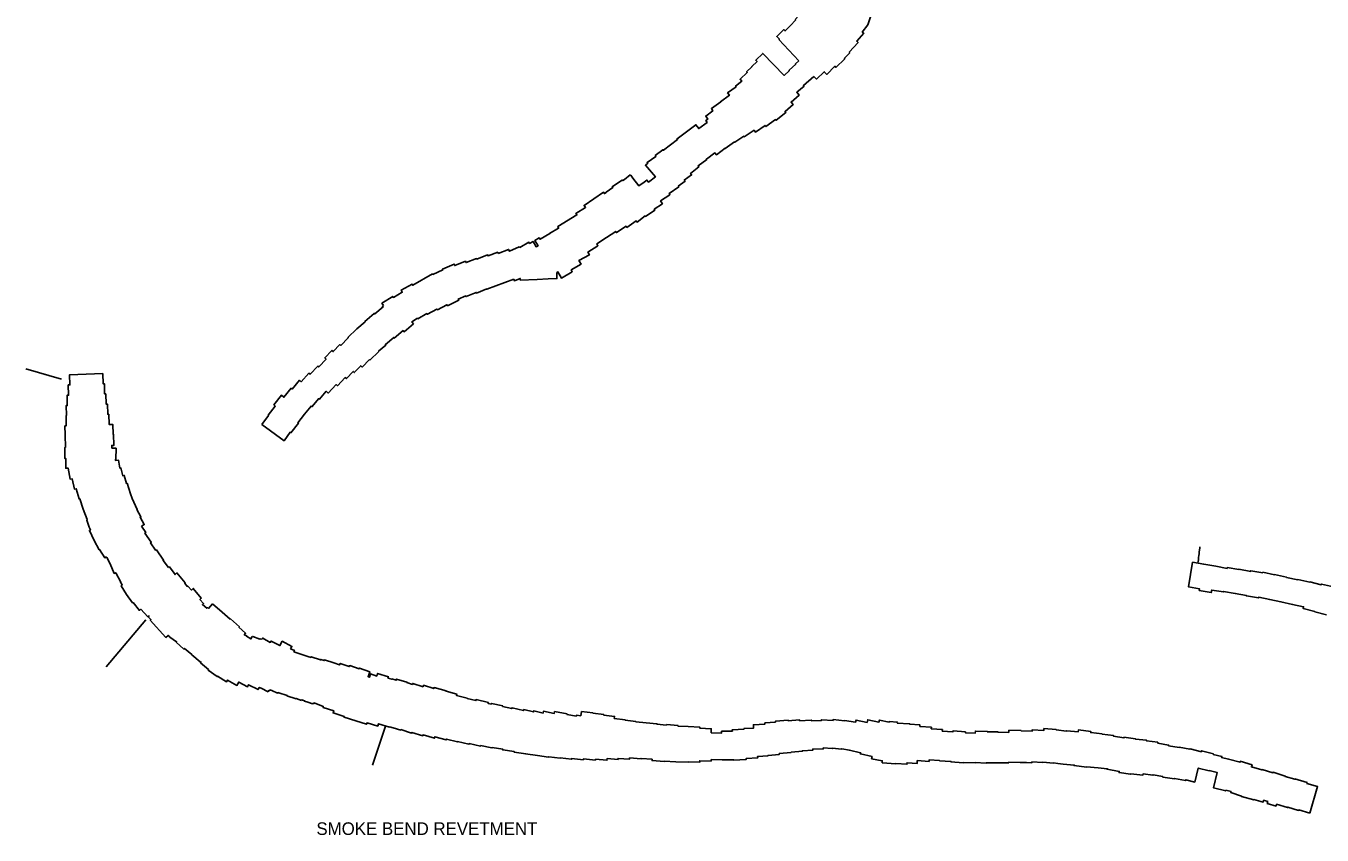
# Model space of a CAD drawing. Extents: x 2650582 to 3923188, y 277893 to 989177.
# Drawn here: x 3374386 to 3390842, y 584850 to 595125 of the extents above; entities that cross this region are included whole.
import ezdxf

# ---------------------------------------------------------------- set-up
doc = ezdxf.new("R2010")
doc.units = 0
doc.layers.add('Level 3', color=7, linetype='Continuous')

msp = doc.modelspace()

# ---------------------------------------------------------------- linework, layer by layer
at = {"layer": 'Level 3'}
for p, q in [((3374837, 590640), (3374386, 590770)), ((3375530, 589764), (3375479, 589764)), ((3375909, 587585), (3375406, 586988)), ((3377460, 586670), (3377471, 586690)), ((3378787, 585739), (3378953, 586234))]:
    msp.add_line(p, q, dxfattribs=at)
for points in [[(3384200, 594680), (3383947, 594951), (3383953, 594956), (3383919, 594992), (3384008, 595078), (3384024, 595061), (3384088, 595125), (3384087, 595126), (3384160, 595202), (3384154, 595208), (3384239, 595299), (3384248, 595290), (3384314, 595360), (3384312, 595361), (3384416, 595473), (3384440, 595450), (3384519, 595529), (3384494, 595553), (3384532, 595594)], [(3385108, 595385), (3385106, 595298), (3385125, 595292), (3385077, 595140), (3385072, 595141), (3385076, 595137), (3385004, 595047), (3385023, 595031), (3384935, 594931), (3384952, 594916), (3384839, 594790), (3384845, 594784), (3384777, 594715), (3384782, 594708), (3384669, 594598), (3384656, 594612), (3384553, 594510), (3384521, 594543), (3384423, 594450), (3384390, 594483)], [(3382376, 593481), (3382474, 593553), (3382479, 593546), (3382660, 593683), (3382654, 593692), (3382892, 593869), (3382928, 593821), (3383035, 593899), (3383019, 593924), (3383045, 593941), (3383018, 593981), (3383107, 594046), (3383090, 594075), (3383208, 594159), (3383206, 594161), (3383317, 594244), (3383295, 594275), (3383403, 594352), (3383396, 594361), (3383476, 594424), (3383453, 594448), (3383543, 594535), (3383536, 594541), (3383603, 594606), (3383601, 594608), (3383668, 594673), (3383652, 594689), (3383741, 594775), (3384011, 594496), (3384079, 594557), (3384076, 594562), (3384160, 594638), (3384156, 594643), (3384200, 594680)], [(3384390, 594483), (3384258, 594369), (3384265, 594360), (3384173, 594283), (3384202, 594245), (3384101, 594158), (3384126, 594127), (3384025, 594039), (3384034, 594026), (3383910, 593927), (3383903, 593935), (3383782, 593846), (3383771, 593862), (3383650, 593775), (3383631, 593800), (3383504, 593717), (3383500, 593724), (3383387, 593648), (3383384, 593653), (3383264, 593568), (3383262, 593571), (3383153, 593489), (3383133, 593512), (3383026, 593435), (3383030, 593430), (3382919, 593350), (3382929, 593334), (3382824, 593253), (3382837, 593233), (3382744, 593167), (3382755, 593153), (3382669, 593091)], [(3380383, 592236), (3380515, 592287), (3380525, 592263), (3380650, 592321), (3380655, 592313), (3380773, 592377), (3380781, 592364), (3380825, 592389), (3380863, 592321), (3380888, 592334), (3380848, 592402), (3380903, 592433), (3380913, 592417), (3381036, 592488), (3381035, 592491), (3381149, 592556), (3381138, 592576), (3381381, 592726), (3381369, 592744), (3381492, 592821), (3381473, 592846), (3381717, 593016), (3381731, 592995), (3381753, 593010), (3381751, 593013), (3381838, 593074), (3381831, 593083), (3381947, 593163), (3381949, 593160), (3381958, 593167), (3381963, 593160), (3381985, 593175), (3382056, 593232), (3382061, 593227), (3382064, 593229), (3382090, 593191), (3382168, 593094), (3382237, 593141), (3382270, 593167), (3382292, 593140), (3382378, 593210), (3382251, 593356), (3382280, 593381), (3382273, 593391), (3382385, 593468), (3382376, 593481)], [(3382669, 593091), (3382675, 593080), (3382552, 592996), (3382562, 592982), (3382443, 592902), (3382466, 592867), (3382364, 592798), (3382371, 592787), (3382254, 592707), (3382250, 592712), (3382146, 592635), (3382135, 592649), (3382016, 592566), (3382005, 592581), (3381884, 592500), (3381874, 592516), (3381757, 592440), (3381759, 592438), (3381634, 592357), (3381648, 592334), (3381521, 592254), (3381541, 592220), (3381408, 592145), (3381435, 592100), (3381310, 592027), (3381323, 592004), (3381185, 591923), (3381141, 592002), (3381125, 591992), (3381128, 591917), (3381015, 591913), (3380879, 591906), (3380663, 591897), (3380662, 591918), (3380588, 591889), (3380580, 591911)], [(3378924, 591575), (3378906, 591603), (3379044, 591690), (3379051, 591678), (3379165, 591744), (3379151, 591770), (3379289, 591846), (3379297, 591832), (3379548, 591976), (3379551, 591970), (3379679, 592026), (3379675, 592035), (3379824, 592100), (3379831, 592082), (3379967, 592136), (3379974, 592120), (3380107, 592171), (3380109, 592165), (3380248, 592217), (3380254, 592204), (3380377, 592252), (3380383, 592236)], [(3380580, 591911), (3380240, 591782), (3380239, 591786), (3380106, 591732), (3380103, 591741), (3379974, 591688), (3379970, 591696), (3379876, 591657), (3379883, 591644), (3379739, 591571), (3379731, 591584), (3379612, 591520), (3379605, 591529), (3379483, 591463), (3379478, 591473), (3379360, 591406), (3379357, 591412), (3379284, 591367), (3379306, 591340)], [(3377382, 590063), (3377466, 590179), (3377462, 590182), (3377552, 590298), (3377534, 590312), (3377629, 590435), (3377662, 590410), (3377752, 590525), (3377766, 590514), (3377860, 590626), (3377882, 590606), (3377979, 590714), (3377993, 590701), (3378093, 590805), (3378104, 590796), (3378197, 590893), (3378180, 590910), (3378272, 591005), (3378288, 590990), (3378373, 591079), (3378385, 591068), (3378478, 591165), (3378475, 591168), (3378586, 591278), (3378587, 591278), (3378694, 591369), (3378691, 591373), (3378809, 591474), (3378815, 591468), (3378921, 591557), (3378913, 591566), (3378924, 591575)], [(3379306, 591340), (3379188, 591241), (3379174, 591257), (3379061, 591162), (3379056, 591169), (3378951, 591081), (3378957, 591072), (3378863, 590993), (3378865, 590991), (3378753, 590881), (3378747, 590888), (3378656, 590792), (3378638, 590810), (3378555, 590722), (3378541, 590737), (3378455, 590646), (3378440, 590660), (3378340, 590556), (3378326, 590570), (3378224, 590463), (3378200, 590486), (3378112, 590385), (3378103, 590393), (3378017, 590290), (3378007, 590298), (3377925, 590193), (3377923, 590194), (3377840, 590087), (3377846, 590082), (3377750, 589959), (3377741, 589965), (3377664, 589857), (3377382, 590063)], [(3374607, 590707), (3374632, 590699)], [(3375362, 590711), (3374940, 590696), (3374945, 590566), (3374923, 590566), (3374927, 590436), (3374908, 590435), (3374912, 590305), (3374896, 590304), (3374900, 590177), (3374896, 590176), (3374899, 590084), (3374898, 590084), (3374897, 590046), (3374882, 590045), (3374886, 589932), (3374883, 589932), (3374890, 589773)], [(3375479, 589764), (3375477, 589798), (3375503, 589799), (3375498, 589939), (3375493, 589939), (3375488, 590064), (3375452, 590063), (3375452, 590064), (3375442, 590065), (3375437, 590193), (3375426, 590193), (3375421, 590323), (3375405, 590322), (3375400, 590452), (3375386, 590452), (3375382, 590582), (3375367, 590581), (3375362, 590711)], [(3374890, 589773), (3374882, 589773), (3374880, 589633), (3374893, 589633), (3374892, 589508), (3374924, 589508), (3374948, 589371), (3374972, 589375), (3375002, 589243), (3375025, 589248), (3375061, 589118), (3375070, 589120), (3375114, 588987), (3375115, 588988), (3375165, 588857), (3375166, 588857), (3375168, 588852)], [(3375855, 588772), (3375889, 588792), (3375835, 588885), (3375846, 588890), (3375796, 588985), (3375797, 588986), (3375735, 589125), (3375735, 589124), (3375712, 589183), (3375715, 589184), (3375671, 589317), (3375662, 589315), (3375634, 589417), (3375615, 589412), (3375593, 589513), (3375578, 589510), (3375560, 589611), (3375524, 589605), (3375524, 589623), (3375528, 589623), (3375530, 589764)], [(3375168, 588852), (3375158, 588848), (3375191, 588761), (3375188, 588759), (3375202, 588734), (3375205, 588724), (3375193, 588718), (3375253, 588591), (3375253, 588591), (3375318, 588474), (3375321, 588476), (3375387, 588372), (3375404, 588382), (3375410, 588371), (3375412, 588373), (3375457, 588296)], [(3376197, 588247), (3376128, 588337), (3376135, 588342), (3376043, 588472), (3376033, 588466), (3375966, 588561), (3375977, 588568), (3375898, 588685), (3375908, 588692), (3375855, 588772)], [(3389291, 588512), (3389289, 588495), (3389286, 588471), (3389283, 588443), (3389280, 588421), (3389278, 588401), (3389275, 588374), (3389271, 588346), (3389269, 588326), (3389266, 588309)], [(3375457, 588296), (3375454, 588294), (3375508, 588173), (3375526, 588181), (3375590, 588062), (3375586, 588060), (3375610, 588026), (3375594, 588016), (3375663, 587906), (3375662, 587905)], [(3390900, 587648), (3390748, 587686), (3390749, 587691), (3390603, 587726), (3390608, 587749), (3390468, 587778), (3390468, 587780), (3390320, 587810), (3390320, 587812), (3390178, 587842), (3390178, 587840), (3390037, 587870), (3390036, 587861), (3389881, 587887), (3389882, 587894), (3389740, 587918), (3389739, 587917), (3389591, 587944), (3389590, 587937), (3389441, 587962), (3389435, 587929), (3389282, 587956), (3389285, 587979), (3389144, 588003), (3389198, 588314)], [(3389198, 588314), (3389339, 588289), (3389340, 588291), (3389494, 588264), (3389494, 588263), (3389636, 588237), (3389638, 588247), (3389786, 588221), (3389787, 588225), (3389936, 588199), (3389937, 588207), (3390089, 588181), (3390090, 588187), (3390238, 588156), (3390239, 588157), (3390392, 588125), (3390391, 588123), (3390534, 588093), (3390534, 588094), (3390686, 588062), (3390687, 588065), (3390832, 588029), (3390834, 588038), (3390986, 588001)], [(3376756, 587787), (3376704, 587728), (3376691, 587740), (3376682, 587730), (3376627, 587780), (3376641, 587792), (3376595, 587843), (3376613, 587858), (3376511, 587982), (3376487, 587962), (3376441, 588013), (3376435, 588008), (3376402, 588050), (3376406, 588053), (3376303, 588179), (3376280, 588159), (3376209, 588255), (3376197, 588247)], [(3375662, 587905), (3375740, 587798), (3375747, 587803), (3375828, 587702), (3375847, 587717), (3375933, 587622), (3375949, 587635), (3375950, 587633), (3375940, 587623), (3375973, 587589), (3375964, 587581), (3376164, 587360), (3376192, 587385), (3376204, 587374), (3376203, 587373), (3376213, 587366), (3376215, 587364), (3376215, 587364), (3376299, 587305), (3376295, 587300), (3376393, 587212), (3376401, 587221), (3376493, 587143), (3376491, 587140), (3376598, 587050), (3376601, 587053)], [(3377157, 587394), (3377175, 587414), (3377091, 587489), (3377096, 587495), (3376982, 587595), (3376980, 587592), (3376878, 587682), (3376877, 587680), (3376756, 587787)], [(3377747, 587214), (3377764, 587245), (3377640, 587311), (3377611, 587256), (3377499, 587314), (3377489, 587296), (3377392, 587352), (3377383, 587336), (3377360, 587344), (3377358, 587337), (3377267, 587372), (3377265, 587368), (3377260, 587371), (3377243, 587341), (3377188, 587375), (3377190, 587379), (3377159, 587393), (3377157, 587394)], [(3379222, 586788), (3379223, 586792), (3379091, 586832), (3379086, 586817), (3379033, 586833), (3379031, 586828), (3378983, 586843), (3378988, 586860), (3378851, 586903), (3378841, 586870), (3378761, 586896), (3378747, 586855), (3378730, 586861), (3378752, 586924), (3378620, 586971), (3378616, 586961), (3378498, 587002), (3378496, 586997), (3378494, 586998), (3378492, 586989), (3378376, 587030), (3378369, 587010), (3378294, 587036), (3378294, 587038), (3378176, 587074), (3378173, 587066), (3378129, 587081), (3378127, 587074), (3378008, 587114), (3378006, 587106), (3377964, 587118), (3377964, 587116), (3377900, 587138), (3377901, 587139), (3377788, 587178), (3377795, 587195), (3377747, 587214)], [(3376601, 587053), (3376608, 587047), (3376601, 587039), (3376706, 586951), (3376701, 586944), (3376815, 586862), (3376819, 586868), (3376934, 586797), (3376947, 586818), (3377065, 586751), (3377089, 586793), (3377198, 586731), (3377214, 586759), (3377333, 586697), (3377348, 586726), (3377373, 586715), (3377374, 586716), (3377460, 586670)], [(3377471, 586690), (3377480, 586686), (3377483, 586693), (3377493, 586689), (3377494, 586690), (3377510, 586684), (3377582, 586653), (3377584, 586659), (3377587, 586658), (3377588, 586659), (3377597, 586656), (3377597, 586655), (3377701, 586623), (3377700, 586619), (3377818, 586582), (3377819, 586586), (3377886, 586558)], [(3380294, 586512), (3380254, 586521), (3380257, 586535), (3380102, 586570), (3380099, 586557), (3379989, 586583), (3379990, 586588), (3379851, 586624), (3379856, 586641), (3379721, 586677), (3379722, 586680), (3379568, 586723), (3379564, 586710), (3379435, 586752), (3379429, 586734), (3379298, 586776), (3379294, 586764), (3379222, 586788)], [(3377886, 586558), (3377890, 586569), (3377924, 586556), (3377923, 586551), (3377967, 586539), (3378023, 586517), (3378025, 586523), (3378042, 586519), (3378045, 586528), (3378162, 586483), (3378159, 586472), (3378294, 586428), (3378286, 586402), (3378428, 586355), (3378425, 586347), (3378573, 586300), (3378574, 586302), (3378712, 586258), (3378717, 586277), (3378854, 586235), (3378862, 586263), (3379003, 586221), (3379004, 586224), (3379047, 586211), (3379047, 586214), (3379146, 586183), (3379148, 586190), (3379283, 586146), (3379286, 586154), (3379425, 586111), (3379429, 586122), (3379572, 586080), (3379577, 586098), (3379722, 586059), (3379725, 586070), (3379865, 586033), (3379867, 586038), (3380011, 586003), (3380014, 586013), (3380158, 585981), (3380159, 585987), (3380303, 585956), (3380304, 585962), (3380442, 585939), (3380441, 585932), (3380585, 585911), (3380584, 585904), (3380731, 585883), (3380730, 585880)], [(3380952, 586398), (3380834, 586427), (3380831, 586414), (3380708, 586443), (3380705, 586432), (3380558, 586468), (3380555, 586456), (3380437, 586484), (3380439, 586490), (3380296, 586523), (3380294, 586512)], [(3381439, 586421), (3381431, 586365), (3381377, 586374), (3381375, 586362), (3381255, 586383), (3381256, 586388), (3381097, 586418), (3381093, 586395), (3380957, 586423), (3380952, 586398)], [(3383084, 586150), (3383087, 586200), (3382942, 586209), (3382943, 586220), (3382795, 586231), (3382794, 586227), (3382664, 586235), (3382665, 586243), (3382519, 586253), (3382518, 586246), (3382397, 586258), (3382397, 586263), (3382260, 586277), (3382128, 586290), (3382129, 586293), (3381993, 586311), (3381994, 586315), (3381856, 586331), (3381859, 586356), (3381722, 586374), (3381723, 586381), (3381585, 586399), (3381585, 586401), (3381439, 586421)], [(3386865, 586153), (3386729, 586155), (3386729, 586160), (3386592, 586163), (3386592, 586166), (3386440, 586171), (3386439, 586145), (3386313, 586149), (3386314, 586161), (3386157, 586172), (3386156, 586162), (3386020, 586171), (3386021, 586189), (3385881, 586201), (3385882, 586220), (3385736, 586230), (3385737, 586249), (3385604, 586259), (3385604, 586263), (3385449, 586273), (3385450, 586285), (3385347, 586294), (3385347, 586286), (3385221, 586311), (3385216, 586284), (3385073, 586315), (3385066, 586281), (3384925, 586311), (3384920, 586285), (3384780, 586307), (3384778, 586299), (3384634, 586316), (3384633, 586306), (3384486, 586315), (3384485, 586305), (3384357, 586303), (3384356, 586310), (3384208, 586303), (3384208, 586312), (3384064, 586299), (3384063, 586310), (3383902, 586296), (3383902, 586286), (3383767, 586275)], [(3383767, 586275), (3383768, 586260), (3383623, 586252), (3383625, 586209), (3383502, 586204), (3383503, 586193), (3383354, 586187), (3383355, 586170), (3383219, 586169), (3383219, 586146), (3383084, 586150)], [(3389655, 585813), (3389567, 585834), (3389571, 585848), (3389461, 585875), (3389463, 585881), (3389312, 585920), (3389309, 585909), (3389167, 585946), (3389165, 585940), (3389027, 585966), (3389027, 585963), (3388893, 585984), (3388894, 585994), (3388755, 586018), (3388756, 586029), (3388611, 586049), (3388611, 586056), (3388473, 586069), (3388474, 586072), (3388327, 586093), (3388326, 586084), (3388193, 586108), (3388194, 586114), (3388049, 586133), (3388049, 586134), (3387904, 586151), (3387906, 586167), (3387749, 586186), (3387745, 586160), (3387600, 586175), (3387599, 586170), (3387466, 586185), (3387467, 586190), (3387310, 586203), (3387308, 586177), (3387161, 586185), (3387160, 586169), (3387020, 586174), (3387020, 586177), (3386865, 586181), (3386865, 586153)], [(3380730, 585880), (3380880, 585859), (3380880, 585860), (3381022, 585841), (3381023, 585845), (3381169, 585828), (3381169, 585829), (3381313, 585813), (3381314, 585823), (3381464, 585806), (3381465, 585817), (3381617, 585803), (3381618, 585814), (3381762, 585801), (3381764, 585822), (3381904, 585811), (3381905, 585824), (3382048, 585813), (3382050, 585831), (3382196, 585820), (3382196, 585823), (3382336, 585813), (3382335, 585797), (3382488, 585786), (3382488, 585787), (3382639, 585779), (3382639, 585780), (3382792, 585774), (3382792, 585780), (3382940, 585774), (3382941, 585795), (3383085, 585789), (3383086, 585809), (3383225, 585805), (3383225, 585806), (3383371, 585807), (3383371, 585802), (3383529, 585809), (3383529, 585822), (3383677, 585829), (3383676, 585849), (3383808, 585856)], [(3383808, 585856), (3383808, 585862), (3383951, 585874), (3383950, 585885), (3384100, 585899), (3384100, 585901), (3384245, 585915), (3384244, 585921), (3384376, 585927), (3384375, 585943), (3384508, 585944), (3384508, 585956), (3384624, 585949), (3384624, 585954), (3384743, 585940), (3384743, 585946), (3384842, 585930), (3384841, 585927), (3384983, 585896), (3384980, 585881), (3385128, 585849), (3385122, 585820), (3385259, 585793), (3385257, 585768), (3385430, 585753), (3385431, 585757), (3385572, 585749), (3385574, 585769), (3385701, 585759), (3385703, 585796), (3385852, 585786), (3385854, 585807), (3385985, 585797), (3385985, 585795), (3386129, 585786), (3386129, 585780), (3386286, 585769), (3386286, 585771), (3386436, 585766), (3386436, 585770), (3386579, 585765), (3386579, 585769), (3386719, 585767), (3386719, 585768), (3386864, 585766)], [(3390686, 585129), (3390784, 585466), (3390649, 585505), (3390652, 585516), (3390497, 585563), (3390496, 585559), (3390372, 585596), (3390374, 585600), (3390219, 585647), (3390217, 585642), (3390080, 585682), (3390079, 585678), (3389945, 585716), (3389953, 585742), (3389804, 585788), (3389800, 585774), (3389655, 585816), (3389655, 585813)], [(3386864, 585766), (3386864, 585775), (3387009, 585771), (3387009, 585773), (3387088, 585771), (3387158, 585769), (3387158, 585779), (3387297, 585772), (3387297, 585776), (3387433, 585765), (3387433, 585766), (3387486, 585760), (3387556, 585752), (3387556, 585752), (3387695, 585738), (3387694, 585732), (3387851, 585714), (3387852, 585718), (3388001, 585702), (3388001, 585706), (3388114, 585692), (3388113, 585687), (3388267, 585659), (3388265, 585643), (3388411, 585622), (3388412, 585627), (3388568, 585612), (3388570, 585627), (3388695, 585610), (3388696, 585616), (3388819, 585594), (3388818, 585587), (3388968, 585563), (3388969, 585570), (3389109, 585543), (3389110, 585553), (3389225, 585523), (3389270, 585700), (3389408, 585666), (3389409, 585670), (3389512, 585644), (3389464, 585448), (3389619, 585411), (3389622, 585422)], [(3389622, 585422), (3389687, 585403), (3389682, 585389), (3389820, 585346), (3389819, 585342), (3389975, 585297), (3389977, 585303), (3390094, 585269), (3390100, 585292), (3390153, 585275), (3390145, 585252), (3390258, 585218), (3390265, 585242), (3390404, 585200), (3390405, 585205), (3390544, 585163), (3390546, 585170), (3390686, 585129)]]:
    msp.add_lwpolyline(points, dxfattribs=at)

# ---------------------------------------------------------------- texts
msp.add_text('SMOKE BEND REVETMENT', height=160, dxfattribs=at).set_placement((3378074, 584852))

doc.saveas('drawing.dxf')
